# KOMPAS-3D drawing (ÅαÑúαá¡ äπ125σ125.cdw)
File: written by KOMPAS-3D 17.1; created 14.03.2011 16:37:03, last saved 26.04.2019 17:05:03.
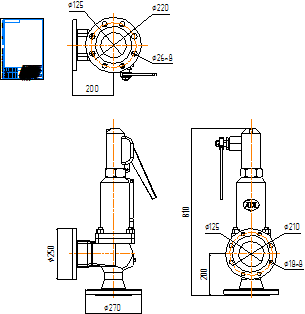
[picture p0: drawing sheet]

Sheet 1: A4, portrait

Title block, sheet 1: name: Прегран Ду125х125; material: Внимание! Данный продукт является объектом авторского права ООО «Торговый Дом АДЛ». / Запрещается изменение, копирование, распространение / (в том числе путем копирования на другие сайты и ресурсы в Интернете) / или любое иное использование информации и объектов без предварительного / согласия правообладателя (ООО «Торговый Дом АДЛ»).; scale: 1:1; sheets: 1; organisation: ООО "Торговый дом АДЛ"; sheet format: A4; stored path: C:\Users\tra\Desktop\2д чертежи\Предохранительные клапаны ПРЕГРАН\ПРЕГРАН 096\ПРЕГРАН КПП 096-03-40\KOMPAS 2D\Прегран Ду125х125.cdw

Views: Проекционный вид 3, Проекционный вид 4, Проекционный вид 5
Dimensions and other numbers on the sheet: 200; 810; 270; 250; 220; 26; 125; 210; 18; 1:1; 1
